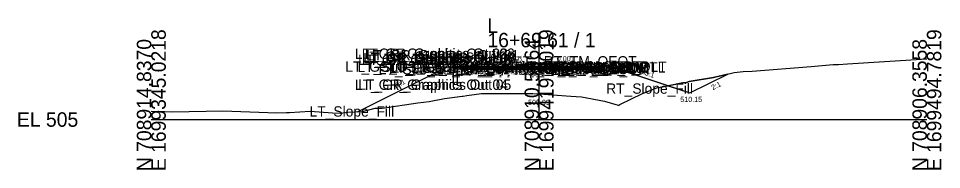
# Model space of a CAD drawing. Extents: x -63 to 1153, y -24 to 9522.
# Drawn here: x -25.7 to 152.8, y 8490.3 to 8519.6 of the extents above; entities that cross this region are included whole.
import ezdxf

# ---------------------------------------------------------------- set-up
doc = ezdxf.new("R2010")
doc.units = 0
for name, color, linetype in [('Default', 7, 'Continuous'), ('Exist Cross Section Cell', 7, 'Continuous'), ('Exist XS Center Line Elevation Label', 7, 'Continuous'), ('Exist XS Ground Line', 7, 'Continuous'), ('Prop CMT DNC', 7, 'Continuous'), ('Prop CMT Guardrail Graphics', 7, 'Continuous'), ('Prop CMT Pvmt Course 1', 7, 'Continuous'), ('Prop CMT Pvmt Course 2', 7, 'Continuous'), ('Prop CMT Pvmt Surface', 7, 'Continuous'), ('Prop CMT Pvmt Surface Overlay', 7, 'Continuous'), ('Prop CMT Pvmt Surface Shoulder', 7, 'Continuous'), ('Prop CMT Shld Paved Course 1', 7, 'Continuous'), ('Prop CMT Shld Paved Course 2', 7, 'Continuous'), ('Prop CMT Slope Grass', 7, 'Continuous'), ('Prop CMT Subgrade Earthwork', 7, 'Continuous'), ('Prop XS Ditch Standard Text', 7, 'Continuous'), ('Prop XS Earthwork Shape', 7, 'Continuous'), ('Prop XS EOT Tick Mark', 7, 'Continuous'), ('Prop XS SE Text', 7, 'Continuous'), ('Prop XS Side Slope Text', 7, 'Continuous')]:
    doc.layers.add(name, color=color, linetype=linetype)

msp = doc.modelspace()

# ---------------------------------------------------------------- linework, layer by layer
at = {"layer": 'Exist Cross Section Cell'}
for p, q in [((75, 8500), (75, 8516.79)), ((0, 8500), (75, 8500)), ((75, 8500), (150, 8500))]:
    msp.add_line(p, q, dxfattribs=at)
at = {"layer": 'Exist XS Ground Line'}
msp.add_lwpolyline([(0, 8501.6), (2.56, 8501.57), (4.11, 8501.51), (13.85, 8501.71), (24.25, 8501.29), (26.18, 8501.34), (26.71, 8501.34), (30.74, 8501.6), (35.04, 8501.32), (36.59, 8501.22), (38.04, 8501.41), (40.87, 8501.55), (43.3, 8502.18), (44.64, 8502.22), (51.52, 8503.26), (53.74, 8503.51), (56.68, 8504.09), (60.15, 8504.52), (60.32, 8504.55), (61, 8504.63), (63.89, 8505.04), (73.55, 8505.07), (73.79, 8505.07), (75, 8504.99), (81.12, 8504.55), (83.18, 8504.4), (83.19, 8504.4), (83.2, 8504.4), (87.65, 8503.59), (90.32, 8502.81), (90.41, 8502.78), (90.61, 8502.89), (95.02, 8505.06), (97.8, 8506.12), (102.79, 8507.1), (103.51, 8507.19), (104.04, 8507.35), (108.75, 8508.15), (112.7, 8509.11), (114.47, 8509.29), (116.22, 8509.37), (127.63, 8510.25), (131.88, 8510.64), (132.28, 8510.66), (132.89, 8510.68), (134.68, 8510.81), (150, 8511.75)], dxfattribs=at)
at = {"layer": 'Prop CMT Guardrail Graphics'}
for points in [[(58.47, 8512.75), (59.8, 8512.76), (60.08, 8512.46)], [(58.47, 8506.75), (58.47, 8512.75)], [(60.08, 8512.46), (59.8, 8512.17)], [(60.08, 8511.88), (59.8, 8511.59), (59.14, 8511.59)], [(59.14, 8511.59), (59.14, 8506.76)], [(59.8, 8512.17), (60.08, 8511.88)], [(59.14, 8506.76), (58.47, 8506.75)]]:
    msp.add_lwpolyline(points, dxfattribs=at)
at = {"layer": 'Prop CMT Pvmt Course 1'}
for points in [[(75, 8510.28), (65, 8510.27)], [(65, 8510.27), (65, 8510.02)], [(65, 8510.02), (75, 8510.03)], [(75, 8510.15), (75, 8510.28)], [(75, 8510.28), (85, 8510.28)], [(75, 8510.15), (75, 8510.28)], [(75, 8510.03), (75, 8510.15), (75, 8510.15)], [(75, 8510.03), (75, 8510.15), (75, 8510.15)], [(85, 8510.03), (75, 8510.03)], [(85, 8510.28), (85, 8510.03)]]:
    msp.add_lwpolyline(points, dxfattribs=at)
at = {"layer": 'Prop CMT Pvmt Course 2'}
for points in [[(75, 8510.03), (65, 8510.02)], [(65, 8510.02), (65, 8509.77)], [(65, 8509.77), (75, 8509.78)], [(75, 8509.78), (75, 8510.03)], [(75, 8509.78), (75, 8510.03)], [(75, 8510.03), (85, 8510.03)], [(85, 8509.78), (75, 8509.78)], [(85, 8510.03), (85, 8509.78)]]:
    msp.add_lwpolyline(points, dxfattribs=at)
at = {"layer": 'Prop CMT Pvmt Surface'}
for points in [[(75, 8510.28), (65, 8510.27)], [(75, 8510.28), (85, 8510.28)]]:
    msp.add_lwpolyline(points, dxfattribs=at)
at = {"layer": 'Prop CMT Pvmt Surface Overlay'}
for points in [[(75, 8510.28), (65, 8510.27)], [(75, 8510.28), (85, 8510.28)]]:
    msp.add_lwpolyline(points, dxfattribs=at)
at = {"layer": 'Prop CMT Pvmt Surface Shoulder'}
for points in [[(65, 8510.27), (60.27, 8510.27)], [(85, 8510.28), (86.27, 8510.28)]]:
    msp.add_lwpolyline(points, dxfattribs=at)
at = {"layer": 'Prop CMT Shld Paved Course 1'}
for points in [[(65, 8510.27), (60.27, 8510.27), (60.02, 8510.02)], [(60.02, 8510.02), (65, 8510.02)], [(65, 8510.02), (65, 8510.27)], [(85, 8510.28), (86.27, 8510.28), (86.52, 8510.03)], [(85, 8510.03), (85, 8510.28)], [(86.52, 8510.03), (85, 8510.03)]]:
    msp.add_lwpolyline(points, dxfattribs=at)
at = {"layer": 'Prop CMT Shld Paved Course 2'}
for points in [[(60.02, 8510.02), (59.77, 8509.77)], [(59.77, 8509.77), (65, 8509.77)], [(65, 8510.02), (60.02, 8510.02)], [(60.02, 8510.02), (60.02, 8510.02)], [(65, 8509.77), (65, 8510.02)], [(85, 8510.03), (86.52, 8510.03)], [(85, 8509.78), (85, 8510.03)], [(86.77, 8509.78), (85, 8509.78)], [(86.52, 8510.03), (86.52, 8510.03)], [(86.52, 8510.03), (86.77, 8509.78)]]:
    msp.add_lwpolyline(points, dxfattribs=at)
at = {"layer": 'Prop CMT Slope Grass'}
for p, q in [((89.3, 8510.1), (104.16, 8505.15)), ((104.16, 8505.15), (111.5, 8508.82))]:
    msp.add_line(p, q, dxfattribs=at)
for points in [[(57.08, 8510.07), (39.95, 8501.5)], [(60.08, 8510.26), (57.08, 8510.07)], [(60.27, 8510.27), (60.08, 8510.26)], [(86.27, 8510.28), (89.3, 8510.1)]]:
    msp.add_lwpolyline(points, dxfattribs=at)
at = {"layer": 'Prop CMT Subgrade Earthwork'}
for points in [[(59.77, 8509.77), (59.33, 8510.21)], [(65, 8509.77), (59.77, 8509.77)], [(75, 8509.78), (65, 8509.77)], [(75, 8509.78), (85, 8509.78)], [(85, 8509.78), (86.77, 8509.78)], [(86.77, 8509.78), (87.21, 8510.23)]]:
    msp.add_lwpolyline(points, dxfattribs=at)
at = {"layer": 'Prop XS Earthwork Shape'}
for points in [[(59.33, 8510.21), (57.08, 8510.07), (39.95, 8501.5), (40.87, 8501.55), (43.3, 8502.18), (44.64, 8502.22), (51.52, 8503.26), (53.74, 8503.51), (56.68, 8504.09), (60.15, 8504.52), (60.32, 8504.55), (61, 8504.63), (63.89, 8505.04), (73.55, 8505.07), (73.79, 8505.07), (75, 8504.99), (81.12, 8504.55), (83.18, 8504.4), (83.2, 8504.4), (87.65, 8503.59), (90.32, 8502.81), (90.41, 8502.78), (90.61, 8502.89), (95.02, 8505.06), (97.8, 8506.12), (99.98, 8506.55), (89.3, 8510.1), (87.21, 8510.23), (86.77, 8509.78), (85, 8509.78), (75, 8509.78), (65, 8509.77), (59.77, 8509.77)], [(99.98, 8506.55), (104.16, 8505.15), (111.5, 8508.82), (108.75, 8508.15), (104.04, 8507.35), (103.51, 8507.19), (102.79, 8507.1)]]:
    msp.add_lwpolyline(points, close=True, dxfattribs=at)
at = {"layer": 'Prop XS EOT Tick Mark'}
for points in [[(65, 8510.27), (65, 8511.27)], [(85, 8510.28), (85, 8511.28)]]:
    msp.add_lwpolyline(points, dxfattribs=at)

# ---------------------------------------------------------------- texts
at = {"layer": 'Default'}
msp.add_text('-', height=0.0001, dxfattribs=at).set_placement((0, 8500))
at = {"layer": 'Exist Cross Section Cell'}
for s, p in [('L', (65, 8516.79)), ('16+69.61 / 1', (65, 8513.99)), ('EL 505', (-26, 8498.6))]:
    msp.add_text(s, height=2.8, dxfattribs=at).set_placement(p)
for s, p in [('E 1699345.0218', (2.8, 8490)), ('E 1699419.9019', (77.8, 8490)), ('E 1699494.7819', (152.8, 8490)), ('N 708914.8370', (0, 8490)), ('N 708910.5964', (75, 8490)), ('N 708906.3558', (150, 8490))]:
    msp.add_text(s, height=2.8, rotation=90, dxfattribs=at).set_placement(p)
at = {"layer": 'Exist XS Center Line Elevation Label'}
msp.add_text('509.99', height=1, dxfattribs=at).set_placement((72.87, 8502.83))
at = {"layer": 'Prop CMT DNC'}
for s, p in [('LT_GR_Graphics Out 03', (39.37, 8511.75)), ('LT_GR_Graphics Out 06', (39.99, 8510.59)), ('LT_GR_Graphics Out 02', (40.7, 8511.76)), ('LT_GR_Graphics Out 09', (40.7, 8511.17)), ('LT_GR_Graphics Out 07', (40.7, 8510.59)), ('LT_GR_Graphics Out 08', (40.97, 8510.88)), ('LT_GR_Graphics Out 01', (41.54, 8511.46)), ('LT_GS_OS_GR_Face_Graphics', (37.53, 8509.26)), ('LT_Sub_Trench_Out_DLT', (39.89, 8509.21)), ('LT_Sub_Trench_Out', (43.97, 8508.77)), ('LT_PS2_Shelf_Out', (46, 8509.02)), ('LT_GS_OS_CTL', (46.45, 8509.07)), ('LT_PS2_OEOP', (50.26, 8509.02)), ('LT_PS1_OEOP', (51.07, 8509.27)), ('LT_Sub_OEOT', (55.08, 8508.77)), ('LT_PV2_OEOT', (55.17, 8509.02)), ('LT_PV1_OEOT', (55.74, 8509.27)), ('LT_TM_OEOT', (55.94, 8510.27)), ('RT_PV1_OEEOP_W', (62.94, 8509.15)), ('LT_PV1_OEEOP_W', (62.98, 8509.15)), ('RT_Sub_OEEOP', (64.16, 8508.78)), ('LT_Sub_OEEOP', (64.21, 8508.78)), ('RT_PV2_OEEOP', (64.26, 8509.03)), ('LT_PV2_OEEOP', (64.31, 8509.03)), ('PV1_PGL_W', (67.58, 8509.15)), ('RT_Sub_Trench_Out_DLT', (67.73, 8509.23)), ('PV1_PGL', (69.47, 8509.28)), ('RT_Sub_Trench_Out', (70.93, 8508.78)), ('RT_PS2_Shelf_Out', (72.46, 8509.03)), ('RT_Sub_OEOT', (75.03, 8508.78)), ('RT_PV2_OEOT', (75.13, 8509.03)), ('RT_PV1_OEOT', (75.69, 8509.28)), ('RT_TM_OEOT', (75.9, 8510.28)), ('RT_PS2_OEOP', (76.71, 8509.03)), ('RT_PS1_OEOP', (77.03, 8509.28)), ('RT_GS_OS_CTL', (78.63, 8509.1)), ('LT_GR_Graphics Out 04', (39.37, 8505.75)), ('LT_GR_Graphics Out 05', (40.04, 8505.76)), ('RT_Slope_Fill', (87.98, 8505)), ('LT_Slope_Fill', (30.61, 8500.57))]:
    msp.add_text(s, height=2, dxfattribs=at).set_placement(p)
at = {"layer": 'Prop XS Ditch Standard Text'}
msp.add_text('510.15', height=1, dxfattribs=at).set_placement((102.31, 8503.4))
at = {"layer": 'Prop XS SE Text'}
for rotation, p in [(0.0391, (68.43, 8511.27)), (0.0332, (78.43, 8511.28))]:
    msp.add_text('0.001', height=1, rotation=rotation, dxfattribs=at).set_placement(p)
at = {"layer": 'Prop XS Side Slope Text'}
for s, rotation, p in [('3:1', 341.5651, (95.33, 8508.65)), ('2:1', 26.5865, (47.54, 8506.14)), ('2:1', 26.5651, (108.6, 8505.67))]:
    msp.add_text(s, height=1, rotation=rotation, dxfattribs=at).set_placement(p)

doc.saveas('drawing.dxf')
